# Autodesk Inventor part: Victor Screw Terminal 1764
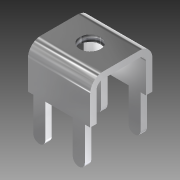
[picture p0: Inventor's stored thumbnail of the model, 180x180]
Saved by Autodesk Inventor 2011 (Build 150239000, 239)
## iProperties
Shininess: 86.0
Length Units: 11272
Angle Units: 11279
Time Units: 11290
Mass Units: 11286
Length Display Precision: 3
Angle Display Precision: 2
Created: 2005-12
Part Number: Victor Screw Terminal 1764
Material: Bronze, Soft Tin
Document SubType Name: Sheet Metal
Designer: t8558es
Density: 1 g/cm^3
Sheet Metal Rule: Default
Density: 0.0
Volumn: 0.0
Area: 0.0
PropertySet Name: Model Information
Control State: 0
Master: False
Checked Out: False
Author: t8558es
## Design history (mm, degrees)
node "Face1"
  sketch "Sketch1"
    geometry: L1 (0, 7.874)-(7.874, 7.874); L2 (7.874, 7.874)-(7.874, 0); L3 (7.874, 0)-(0, 0); L4 (0, 0)-(0, 7.874); 1 further point
    constraints: 8 end point, 2 parallel, 2 point on line, 1 horizontal, 1 perpendicular, 1 other
    dimensions: "d0" = 7.874 distance of L1.start L1.end; "d1" = 7.874 distance of L1.end L2.end
node "Flange1"
node "Flange2"
sketch "Sketch4"
  geometry: L1 (0, -4.623)-(7.874, -4.623) reference; L2 (7.874, -4.623)-(7.874, 0) reference; L3 (7.874, 0)-(0, 0) reference; L4 (0, 0)-(0, -4.623) reference; L5 (3.937, -2.311)-(0, -2.311); L6 (3.937, -2.311)-(7.874, -2.311); L7 (3.937, -2.311)-(3.937, 0); L8 (3.937, -2.311)-(3.937, -4.623)
  constraints: 8 end point, 4 midpoint, 3 collinear, 3 perpendicular
hole "Hole1" sketch "Sketch4" at (3.937, -2.311) diameter "d11" = 2.6416; stored, may be unused: countersink angle "d15" = 82 deg, drill point angle "d17" = 118 deg; dims "d12" = 12.7, "d13" = 9.525, "d14" = 6.35, "d16" = 19.05
node "Flange3"
node "Flange4"
node "Flange5"
node "Flange6"
feature "Corner Round1" dims "d43" = 0.762
body "Solid1"
face "Plate1" dims "Thickness" = 0.8128
sketch "Sketch2"
  geometry: L1 (7.874, 0)-(7.874, -5.334); L2 (7.874, -5.334)-(0, -5.334); 2 other entities
  constraints: 4 end point, 4 other
face "Plate2" dims "d4" = 5.334, "d5" = 90 deg, "d6" = 0.8128 (= BendRadius), "Thickness" = 0.8128, "MinimumRemnant" = 1.6256 (= 2 x Thickness), "BendReliefWidth" = 0.8128 (= Thickness)
bend "Bend1" dims "d3" = 0.8128 (= BendRadius), "d4" = 5.334, "d5" = 90 deg, "d6" = 0.8128 (= BendRadius), "d44" = 0.8128 (= BendReliefWidth), "d45" = 0.4064 (= BendReliefDepth), "d46" = 1.6256 (= MinimumRemnant), "SeamGap" = 0.00508, "Thickness" = 0.8128, "MinimumRemnant" = 1.6256 (= 2 x Thickness), "BendReliefWidth" = 0.8128 (= Thickness)
sketch "Sketch3"
  geometry: L1 (7.874, 0)-(7.874, -5.334); L2 (7.874, -5.334)-(0, -5.334); 2 other entities
  constraints: 4 end point, 4 other
face "Plate3" dims "d8" = 5.334, "d9" = 90 deg, "d10" = 0.8128 (= BendRadius), "Thickness" = 0.8128, "MinimumRemnant" = 1.6256 (= 2 x Thickness), "BendReliefWidth" = 0.8128 (= Thickness)
bend "Bend2" dims "d7" = 0.8128 (= BendRadius), "d8" = 5.334, "d9" = 90 deg, "d10" = 0.8128 (= BendRadius), "d47" = 0.8128 (= BendReliefWidth), "d48" = 0.4064 (= BendReliefDepth), "d49" = 1.6256 (= MinimumRemnant), "SeamGap" = 0.00508, "Thickness" = 0.8128, "MinimumRemnant" = 1.6256 (= 2 x Thickness), "BendReliefWidth" = 0.8128 (= Thickness)
sketch "Sketch5"
  geometry: L1 (0.673, 0)-(2.197, 0); L2 (2.197, 0)-(2.197, 5.004); L3 (2.197, 5.004)-(0.673, 5.004); L4 (0.673, 5.004)-(0.673, 0)
  constraints: 8 end point
face "Plate4" dims "d18" = 0.6731, "d19" = 1.524, "d21" = 5.0038, "d22" = 0, "d23" = 0.8128 (= BendRadius), "Thickness" = 0.8128, "MinimumRemnant" = 1.6256 (= 2 x Thickness), "BendReliefWidth" = 0.8128 (= Thickness)
bend "Bend3" dims "d20" = 0.8128 (= BendRadius), "d21" = 5.0038, "d22" = 0, "d23" = 0.8128 (= BendRadius), "d50" = 0.8128 (= BendReliefWidth), "d51" = 0.4064 (= BendReliefDepth), "d52" = 1.6256 (= MinimumRemnant), "SeamGap" = 0.00508, "Thickness" = 0.8128, "MinimumRemnant" = 1.6256 (= 2 x Thickness), "BendReliefWidth" = 0.8128 (= Thickness)
sketch "Sketch6"
  geometry: L1 (0.673, 0)-(2.197, 0); L2 (2.197, 0)-(2.197, 5.004); L3 (2.197, 5.004)-(0.673, 5.004); L4 (0.673, 5.004)-(0.673, 0)
  constraints: 8 end point
face "Plate5" dims "d25" = 0.6731, "d26" = 1.524, "d28" = 5.0038, "d29" = 0, "d30" = 0.8128 (= BendRadius), "Thickness" = 0.8128, "MinimumRemnant" = 1.6256 (= 2 x Thickness), "BendReliefWidth" = 0.8128 (= Thickness)
bend "Bend4" dims "d27" = 0.8128 (= BendRadius), "d28" = 5.0038, "d29" = 0, "d30" = 0.8128 (= BendRadius), "d53" = 0.8128 (= BendReliefWidth), "d54" = 0.4064 (= BendReliefDepth), "d55" = 1.6256 (= MinimumRemnant), "SeamGap" = 0.00508, "Thickness" = 0.8128, "MinimumRemnant" = 1.6256 (= 2 x Thickness), "BendReliefWidth" = 0.8128 (= Thickness)
sketch "Sketch7"
  geometry: L1 (7.201, 0)-(5.677, 0); L2 (5.677, 0)-(5.677, 5.004); L3 (5.677, 5.004)-(7.201, 5.004); L4 (7.201, 5.004)-(7.201, 0)
  constraints: 8 end point
face "Plate6" dims "d31" = 0.6731, "d32" = 1.524, "d34" = 5.0038, "d35" = 0, "d36" = 0.8128 (= BendRadius), "Thickness" = 0.8128, "MinimumRemnant" = 1.6256 (= 2 x Thickness), "BendReliefWidth" = 0.8128 (= Thickness)
bend "Bend5" dims "d33" = 0.8128 (= BendRadius), "d34" = 5.0038, "d35" = 0, "d36" = 0.8128 (= BendRadius), "d56" = 0.8128 (= BendReliefWidth), "d57" = 0.4064 (= BendReliefDepth), "d58" = 1.6256 (= MinimumRemnant), "SeamGap" = 0.00508, "Thickness" = 0.8128, "MinimumRemnant" = 1.6256 (= 2 x Thickness), "BendReliefWidth" = 0.8128 (= Thickness)
sketch "Sketch8"
  geometry: L1 (0.673, 0)-(2.197, 0); L2 (2.197, 0)-(2.197, 5.004); L3 (2.197, 5.004)-(0.673, 5.004); L4 (0.673, 5.004)-(0.673, 0)
  constraints: 8 end point
face "Plate7" dims "d37" = 0.6731, "d38" = 1.524, "d40" = 5.0038, "d41" = 0, "d42" = 0.8128 (= BendRadius), "Thickness" = 0.8128, "MinimumRemnant" = 1.6256 (= 2 x Thickness), "BendReliefWidth" = 0.8128 (= Thickness)
bend "Bend6" dims "d39" = 0.8128 (= BendRadius), "d40" = 5.0038, "d41" = 0, "d42" = 0.8128 (= BendRadius), "d59" = 0.8128 (= BendReliefWidth), "d60" = 0.4064 (= BendReliefDepth), "d61" = 1.6256 (= MinimumRemnant), "SeamGap" = 0.00508, "Thickness" = 0.8128, "MinimumRemnant" = 1.6256 (= 2 x Thickness), "BendReliefWidth" = 0.8128 (= Thickness)
other parameters: "BendRadius" = 0.8128 (= Thickness), "BendReliefDepth" = 0.4064 (= 0.5 x Thickness), "CornerReliefSize" = 3.2512 (= 4 x Thickness), "TransitionRadius" = 0.8128 (= BendRadius), "d2" = 0.8128 (= BendRadius), "JacobiRadiusSize" = 0.8128 (= Thickness), "GapSize" = 0.8128 (= Thickness)
